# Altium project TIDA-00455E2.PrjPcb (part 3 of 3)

## Sheet uC.SchDoc: uC
size 431 x 279 mm; Date: Not shown in title block; ApprovedBy: Not shown in title block; CheckedBy: Not shown in title block; Author: Not shown in title block; CompanyName: Not shown in title block; DrawnBy: Brian Shaffer; Engineer: Not shown in title block; Organization: Not shown in title block; Address1: Not shown in title block; Address2: Not shown in title block; Address3: Not shown in title block; Address4: Not shown in title block; DocumentNumber: 8; Revision: Use project parameter SCH_Rev; SheetNumber: 8; SheetTotal: 10; PageSetup: Record=PageOptions¦CenterHorizontal=True¦CenterVertical=True¦PrintScale=1.00¦XCorrection=1.00¦YCorrection=1.00¦PrintKind=0¦BorderSize=5000000¦LeftOffset=0¦BottomOffset=0¦Orientation=2¦PaperLength=1000¦PaperWidth=1000¦Scale=100¦PaperSource=15¦PrintQuality=600¦MediaType=1¦DitherType=10¦PaperKind=Letter¦PrintScaleMode=1
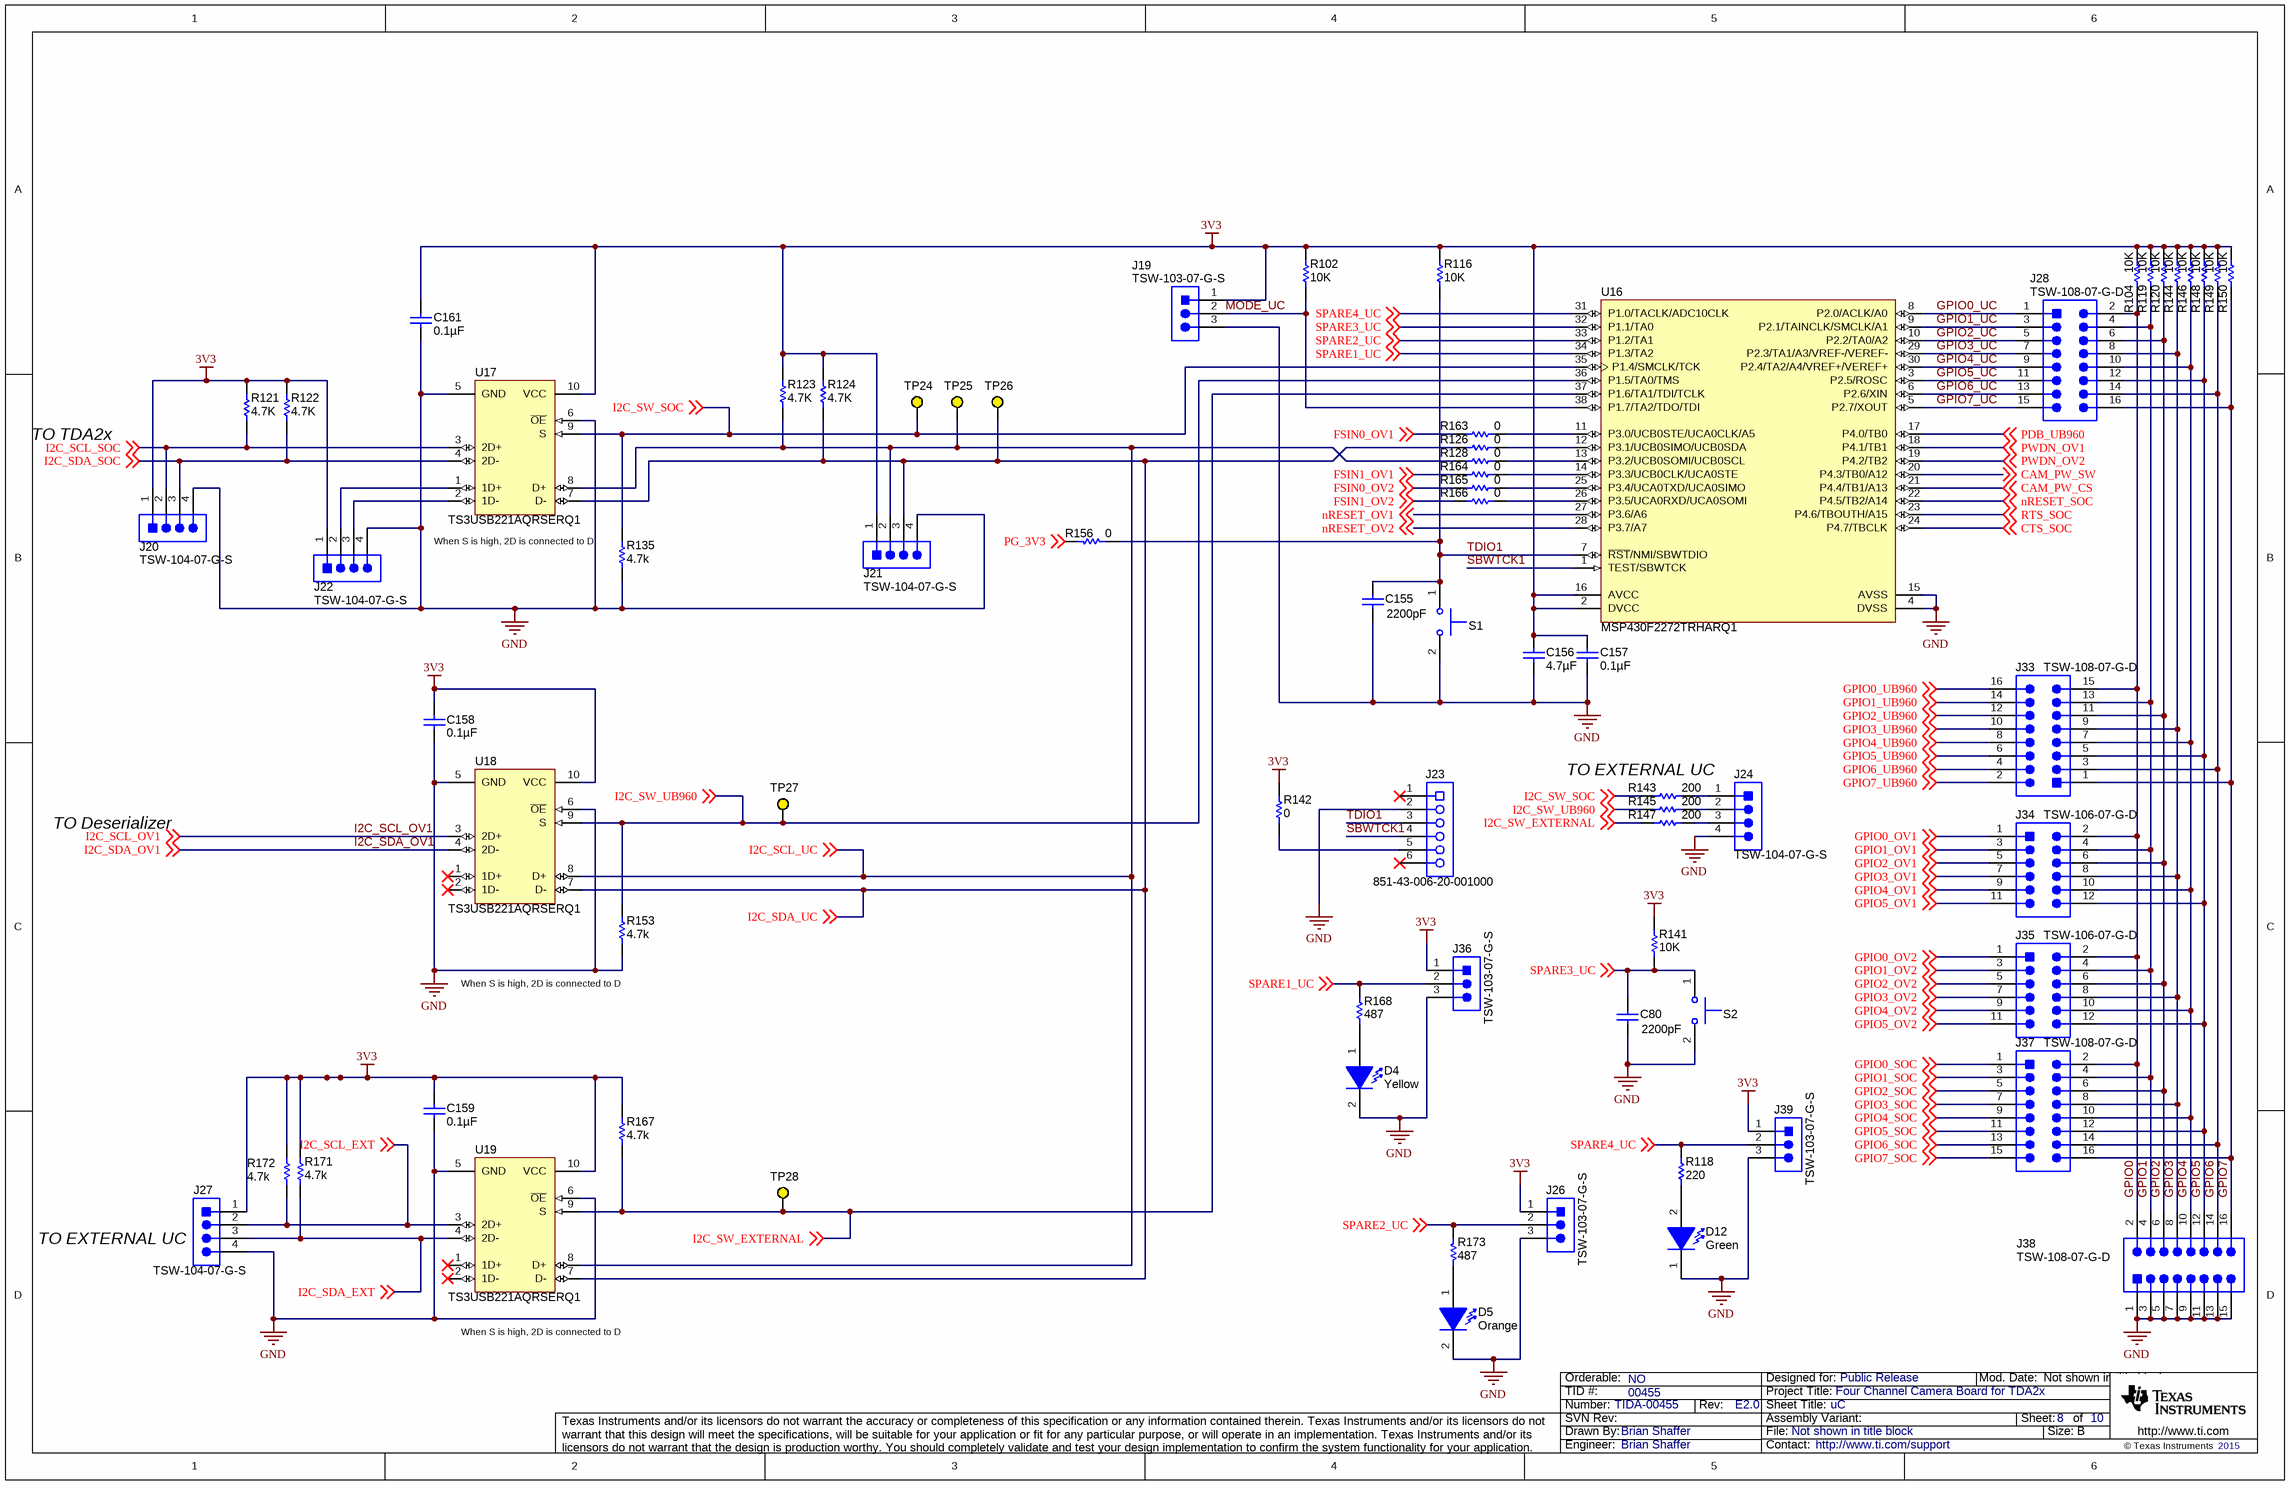
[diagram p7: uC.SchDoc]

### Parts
C80  value 2200pF  [0402]  (hidden comment: UMK105B7222KV-F)
C155  value 2200pF  [0402]  (hidden comment: UMK105B7222KV-F)
C156  ValueDisplayed: 4.7µF  [0805_HV]  (hidden comment: LMK212B7475KG-T)
C157  ValueDisplayed: 0.1µF  [0402]  (hidden comment: GRM155R70J104KA01D)
C158  ValueDisplayed: 0.1µF  [0603]  (hidden comment: 0603YC104JAT2A)
C159  ValueDisplayed: 0.1µF  [0603]  (hidden comment: 0603YC104JAT2A)
C161  ValueDisplayed: 0.1µF  [0603]  (hidden comment: 0603YC104JAT2A)
D4  value Yellow  [LED_SMLP12_Yellow]  (hidden comment: SML-P12YTT86)
D5  value Orange  [LED_SMLP12_ORANGE]  (hidden comment: SML-P12DTT86)
D12  value Green  [SML-P1_GREEN]  (hidden comment: SML-P12PTT86)
J19  TSW-103-07-G-S  [TSW-103-07-G-S]
J20  TSW-104-07-G-S  [TSW-104-07-G-S]
J21  TSW-104-07-G-S  [TSW-104-07-G-S]
J22  TSW-104-07-G-S  [TSW-104-07-G-S]
J23  851-43-006-20-001000  [CONN_851-43-006-20-001000]
J24  TSW-104-07-G-S  [TSW-104-07-G-S]
J26  TSW-103-07-G-S  [TSW-103-07-G-S]
J27  TSW-104-07-G-S  [TSW-104-07-G-S]
J28  TSW-108-07-G-D  [TSW-108-07-G-D]
J33  TSW-108-07-G-D  [TSW-108-07-G-D]
J34  TSW-106-07-G-D  [TSW-106-07-G-D]
J35  TSW-106-07-G-D  [TSW-106-07-G-D]
J36  TSW-103-07-G-S  [TSW-103-07-G-S]
J37  TSW-108-07-G-D  [TSW-108-07-G-D]
J38  TSW-108-07-G-D  [TSW-108-07-G-D]
J39  TSW-103-07-G-S  [TSW-103-07-G-S]
R102  value 10K  [0402]  (hidden comment: CRCW040210K0JNED)
R104  value 10K  [0402]  (hidden comment: CRCW040210K0JNED)
R116  value 10K  [0402]  (hidden comment: CRCW040210K0JNED)
R118  ValueDisplayed: 220  [0402]  (hidden comment: CRCW0402220RJNED)
R119  value 10K  [0402]  (hidden comment: CRCW040210K0JNED)
R120  value 10K  [0402]  (hidden comment: CRCW040210K0JNED)
R121  value 4.7K  [0402]  (hidden comment: CRCW04024K70JNED)
R122  value 4.7K  [0402]  (hidden comment: CRCW04024K70JNED)
R123  value 4.7K  [0402]  (hidden comment: CRCW04024K70JNED)
R124  value 4.7K  [0402]  (hidden comment: CRCW04024K70JNED)
R126  value 0  [0402]  (hidden comment: CRCW04020000Z0ED)
R128  value 0  [0402]  (hidden comment: CRCW04020000Z0ED)
R135  value 4.7k  [0603]  (hidden comment: CRCW06034K70JNEA)
R141  value 10K  [0402]  (hidden comment: CRCW040210K0JNED)
R142  value 0  [0603]  (hidden comment: CRCW06030000Z0EA)
R143  ValueDisplayed: 200  [0402]  (hidden comment: CRCW0402200RJNED)
R144  value 10K  [0402]  (hidden comment: CRCW040210K0JNED)
R145  ValueDisplayed: 200  [0402]  (hidden comment: CRCW0402200RJNED)
R146  value 10K  [0402]  (hidden comment: CRCW040210K0JNED)
R147  ValueDisplayed: 200  [0402]  (hidden comment: CRCW0402200RJNED)
R148  value 10K  [0402]  (hidden comment: CRCW040210K0JNED)
R149  value 10K  [0402]  (hidden comment: CRCW040210K0JNED)
R150  value 10K  [0402]  (hidden comment: CRCW040210K0JNED)
R153  value 4.7k  [0603]  (hidden comment: CRCW06034K70JNEA)
R156  value 0  [0603]  (hidden comment: CRCW06030000Z0EA)
R163  value 0  [0402]  (hidden comment: CRCW04020000Z0ED)
R164  value 0  [0402]  (hidden comment: CRCW04020000Z0ED)
R165  value 0  [0402]  (hidden comment: CRCW04020000Z0ED)
R166  value 0  [0402]  (hidden comment: CRCW04020000Z0ED)
R167  value 4.7k  [0603]  (hidden comment: CRCW06034K70JNEA)
R168  value 487  [0402]  (hidden comment: CRCW0402487RFKED)
R171  value 4.7k  [0603]  (hidden comment: CRCW06034K70JNEA)
R172  value 4.7k  [0603]  (hidden comment: CRCW06034K70JNEA)
R173  value 487  [0402]  (hidden comment: CRCW0402487RFKED)
S1  SKRKAEE010  [SW_SKRKAEE010]  (value not drawn)
S2  SKRKAEE010  [SW_SKRKAEE010]  (value not drawn)
TP24  5004  [Keystone5004]  (value not drawn)
TP25  5004  [Keystone5004]  (value not drawn)
TP26  5004  [Keystone5004]  (value not drawn)
TP27  5004  [Keystone5004]  (value not drawn)
TP28  5004  [Keystone5004]  (value not drawn)
U16  MSP430F2272TRHARQ1  [DA0038A_N]
U17  TS3USB221AQRSERQ1  [RSE0010A]
U18  TS3USB221AQRSERQ1  [RSE0010A]
U19  TS3USB221AQRSERQ1  [RSE0010A]

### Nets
3V3: C156.1 C157.1 C158.1 C159.1 C161.1 J19.1 J20.1 J21.1 J22.1 J26.1 J27.1 J36.1 J39.1 R102.2 R104.2 R116.2 R119.2 R120.2 R121.2 R122.2 R123.2 R124.2 R141.2 R142.2 R144.2 R146.2 R148.2 R149.2 R150.2 R167.2 R171.2 R172.2 U16.2(DVCC) U16.16(AVCC) U17.10(VCC) U18.10(VCC) U19.10(VCC)
GND: C80.2 C155.2 C156.2 C157.2 C158.2 C159.2 C161.2 D4.2(K) D5.2(K) D12.1(K) J19.3 J20.4 J21.4 J22.4 J23.2 J24.4 J26.3 J27.4 J36.3 J38.1 J38.3 J38.5 J38.7 J38.9 J38.11 J38.13 J38.15 J39.3 R135.1 R153.1 S1.2 S2.2 U16.4(DVSS) U16.15(AVSS) U17.5(GND) U17.6(~{OE}) U18.5(GND) U18.6(~{OE}) U19.5(GND) U19.6(~{OE})
CAM_PW_CS: U16.21(P4.4/TB1/A13) ; off-sheet CAM_PW_CS
CAM_PW_SW: U16.20(P4.3/TB0/A12) ; off-sheet CAM_PW_SW
CTS_SOC: U16.24(P4.7/TBCLK) ; off-sheet CTS_SOC
FSIN0_OV1: R163.1 ; off-sheet FSIN0_OV1
FSIN0_OV2: R165.1 ; off-sheet FSIN0_OV2
FSIN1_OV1: R164.1 ; off-sheet FSIN1_OV1
FSIN1_OV2: R166.1 ; off-sheet FSIN1_OV2
GPIO0: J28.2 J33.15 J34.2 J35.2 J37.2 J38.2 R104.1
GPIO0_OV1: J34.1 ; off-sheet GPIO0_OV1
GPIO0_OV2: J35.1 ; off-sheet GPIO0_OV2
GPIO0_SOC: J37.1 ; off-sheet GPIO0_SOC
GPIO0_UB960: J33.16 ; off-sheet GPIO0_UB960
GPIO0_UC: J28.1 U16.8(P2.0/ACLK/A0)
GPIO1: J28.4 J33.13 J34.4 J35.4 J37.4 J38.4 R119.1
GPIO1_OV1: J34.3 ; off-sheet GPIO1_OV1
GPIO1_OV2: J35.3 ; off-sheet GPIO1_OV2
GPIO1_SOC: J37.3 ; off-sheet GPIO1_SOC
GPIO1_UB960: J33.14 ; off-sheet GPIO1_UB960
GPIO1_UC: J28.3 U16.9(P2.1/TAINCLK/SMCLK/A1)
GPIO2: J28.6 J33.11 J34.6 J35.6 J37.6 J38.6 R120.1
GPIO2_OV1: J34.5 ; off-sheet GPIO2_OV1
GPIO2_OV2: J35.5 ; off-sheet GPIO2_OV2
GPIO2_SOC: J37.5 ; off-sheet GPIO2_SOC
GPIO2_UB960: J33.12 ; off-sheet GPIO2_UB960
GPIO2_UC: J28.5 U16.10(P2.2/TA0/A2)
GPIO3: J28.8 J33.9 J34.8 J35.8 J37.8 J38.8 R144.1
GPIO3_OV1: J34.7 ; off-sheet GPIO3_OV1
GPIO3_OV2: J35.7 ; off-sheet GPIO3_OV2
GPIO3_SOC: J37.7 ; off-sheet GPIO3_SOC
GPIO3_UB960: J33.10 ; off-sheet GPIO3_UB960
GPIO3_UC: J28.7 U16.29(P2.3/TA1/A3/VREF-/VEREF-)
GPIO4: J28.10 J33.7 J34.10 J35.10 J37.10 J38.10 R146.1
GPIO4_OV1: J34.9 ; off-sheet GPIO4_OV1
GPIO4_OV2: J35.9 ; off-sheet GPIO4_OV2
GPIO4_SOC: J37.9 ; off-sheet GPIO4_SOC
GPIO4_UB960: J33.8 ; off-sheet GPIO4_UB960
GPIO4_UC: J28.9 U16.30(P2.4/TA2/A4/VREF+/VEREF+)
GPIO5: J28.12 J33.5 J34.12 J35.12 J37.12 J38.12 R148.1
GPIO5_OV1: J34.11 ; off-sheet GPIO5_OV1
GPIO5_OV2: J35.11 ; off-sheet GPIO5_OV2
GPIO5_SOC: J37.11 ; off-sheet GPIO5_SOC
GPIO5_UB960: J33.6 ; off-sheet GPIO5_UB960
GPIO5_UC: J28.11 U16.3(P2.5/ROSC)
GPIO6: J28.14 J33.3 J37.14 J38.14 R149.1
GPIO6_SOC: J37.13 ; off-sheet GPIO6_SOC
GPIO6_UB960: J33.4 ; off-sheet GPIO6_UB960
GPIO6_UC: J28.13 U16.6(P2.6/XIN)
GPIO7: J28.16 J33.1 J37.16 J38.16 R150.1
GPIO7_SOC: J37.15 ; off-sheet GPIO7_SOC
GPIO7_UB960: J33.2 ; off-sheet GPIO7_UB960
GPIO7_UC: J28.15 U16.5(P2.7/XOUT)
I2C_SCL_EXT: J27.2 R172.1 U19.3(2D+) ; off-sheet I2C_SCL_EXT
I2C_SCL_OV1: U18.3(2D+) ; off-sheet I2C_SCL_OV1
I2C_SCL_SOC: J20.2 R121.1 U17.3(2D+) ; off-sheet I2C_SCL_SOC
I2C_SCL_UC: J21.2 R123.1 R128.1 TP25.1 U17.8(D+) U18.8(D+) U19.8(D+) ; off-sheet I2C_SCL_UC
I2C_SDA_EXT: J27.3 R171.1 U19.4(2D-) ; off-sheet I2C_SDA_EXT
I2C_SDA_OV1: U18.4(2D-) ; off-sheet I2C_SDA_OV1
I2C_SDA_SOC: J20.3 R122.1 U17.4(2D-) ; off-sheet I2C_SDA_SOC
I2C_SDA_UC: J21.3 R124.1 R126.1 TP26.1 U17.7(D-) U18.7(D-) U19.7(D-) ; off-sheet I2C_SDA_UC
I2C_SW_EXTERNAL: R147.1 R167.1 TP28.1 U16.37(P1.6/TA1/TDI/TCLK) U19.9(S) ; off-sheet I2C_SW_EXTERNAL
I2C_SW_SOC: R135.2 R143.1 TP24.1 U16.35(P1.4/SMCLK/TCK) U17.9(S) ; off-sheet I2C_SW_SOC
I2C_SW_UB960: R145.1 R153.2 TP27.1 U16.36(P1.5/TA0/TMS) U18.9(S) ; off-sheet I2C_SW_UB960
MODE_UC: J19.2 R102.1 U16.38(P1.7/TA2/TDO/TDI)
nRESET_OV1: U16.27(P3.6/A6) ; off-sheet nRESET_OV1
nRESET_OV2: U16.28(P3.7/A7) ; off-sheet nRESET_OV2
nRESET_SOC: U16.22(P4.5/TB2/A14) ; off-sheet nRESET_SOC
PDB_UB960: U16.17(P4.0/TB0) ; off-sheet PDB_UB960
PG_3V3: R156.2 ; off-sheet PG_3V3
PWDN_OV1: U16.18(P4.1/TB1) ; off-sheet PWDN_OV1
PWDN_OV2: U16.19(P4.2/TB2) ; off-sheet PWDN_OV2
RTS_SOC: U16.23(P4.6/TBOUTH/A15) ; off-sheet RTS_SOC
SBWTCK1: J23.4 U16.1(TEST/SBWTCK)
SPARE1_UC: J36.2 R168.2 U16.34(P1.3/TA2) ; off-sheet SPARE1_UC
SPARE2_UC: J26.2 R173.2 U16.33(P1.2/TA1) ; off-sheet SPARE2_UC
SPARE3_UC: C80.1 R141.1 S2.1 U16.32(P1.1/TA0) ; off-sheet SPARE3_UC
SPARE4_UC: J39.2 R118.2 U16.31(P1.0/TACLK/ADC10CLK) ; off-sheet SPARE4_UC
TDIO1: C155.1 J23.3 R116.1 R156.1 S1.1 U16.7(~{RST}/NMI/SBWTDIO)
NetD4_1: D4.1(A) R168.1
NetD5_1: D5.1(A) R173.1
NetD12_2: D12.2(A) R118.1
NetJ22_2: J22.2 U17.1(1D+)
NetJ22_3: J22.3 U17.2(1D-)
NetJ23_5: J23.5 R142.1
NetJ24_1: J24.1 R143.2
NetJ24_2: J24.2 R145.2
NetJ24_3: J24.3 R147.2
NetR126_2: R126.2 U16.12(P3.1/UCB0SIMO/UCB0SDA)
NetR128_2: R128.2 U16.13(P3.2/UCB0SOMI/UCB0SCL)
NetR163_2: R163.2 U16.11(P3.0/UCB0STE/UCA0CLK/A5)
NetR164_2: R164.2 U16.14(P3.3/UCB0CLK/UCA0STE)
NetR165_2: R165.2 U16.25(P3.4/UCA0TXD/UCA0SIMO)
NetR166_2: R166.2 U16.26(P3.5/UCA0RXD/UCA0SOMI)

Not connected (* = marked no-connect by the designer): J23 1* 6*; U18 1(1D+)* 2(1D-)*; U19 1(1D+)* 2(1D-)*

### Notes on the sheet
- TO TDA2x
- (near R135) When S is high, 2D is connected to D
- (near R143) TO EXTERNAL UC
- TO Deserializer
- (near R153) When S is high, 2D is connected to D
- (near J27) TO EXTERNAL UC
- (near U19) When S is high, 2D is connected to D

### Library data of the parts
C80 C155 = Capacitor: Cap, Cer-X7R, 2200pF, 50V, 10%, 0402; Manufacturer: Taiyo Yuden; PART Name: SCH_LIB\CAP_NP; Polarized: N; U/M: EA; TempCo: X7R; DECAL Name: 0402,0402_HD; EN: 102-1-00062; Onhand: 7818
C156 = LMK212B7475KG-T: Cap, Cer-X7R, 4.7uF, 10V, 10%, 0805; Manufacturer: Taiyo Yuden; PART Name: SCH_LIB\CAP_NP; Polarized: N; CompType: Capacitor; U/M: EA; Cap_F: 0.0000047; Tolerance_%: 10; Value1: Unknown; TempCo: X7R; TaMin_C: -55; TaMax_C: 125; Cap_Case: 0805; EN: 102-1-00281; Onhand: 27
C157 = GRM155R70J104KA01D: Cap, Cer-X7R, 0.1uF, 6.3V, 10%, 0402; Manufacturer: MuRata; Polarized: N; CompType: Capacitor; U/M: EA; Cap_F: 0.0000001; Tolerance_%: 10; Value1: Unknown; VDC_V: 6.3; TempCo: X7R; TaMin_C: -55; TaMax_C: 125; EN: 102-1-01892; Mfg: MURATA MANUFACTURING CO,LTD; Onhand: 0
C158 C159 C161 = 0603YC104JAT2A: CAP, CERM, 0.1uF, 16V, +/-5%, X7R, 0603; Manufacturer: AVX; Polarized: N; CompType: Capacitor; U/M: EA; Cap_F: 0.0000001; Tolerance_%: 5; ESR_Ohm: 0.039; Value1: 0.039 ohm; VDC_V: 16; TaMin_C: -55; TaMax_C: 125
D4 = SML-P12YTT86: LED, Yellow, SMD; Manufacturer: Rohm; Type: InGaN; Vf_V: 2.1; Value2: 2.1V; Io_A: 0.02; Tjmax_C: 85; Value1: W; U/M: EA
D5 = SML-P12DTT86: LED, Orange, SMD; Manufacturer: Rohm; Type: InGaN; Vf_V: 2.1; Value2: 2.1V; Io_A: 0.02; Tjmax_C: 85; Value1: W; U/M: EA
D12 = SML-P12PTT86: LED, Green, SMD; Manufacturer: Rohm; Type: AlInGaP; Vf_V: 2.2; Value2: 2.2V; Io_A: 0.02; Value1: W; U/M: EA
J19 J26 J36 J39 = TSW-103-07-G-S: Header, 100mil, 3x1, Gold, TH; Manufacturer: Samtec; SymbolCreator: a0799628; U/M: EA
J20-J22 J24 J27 = TSW-104-07-G-S: Header, 100mil, 4x1, Gold, TH; Manufacturer: Samtec; SymbolCreator: a0412235; U/M: EA
J23 = 851-43-006-20-001000: Receptacle, 50mil, 6x1, Gold, R/A, TH; Manufacturer: Mill-Max; SymbolCreator: a0411947; U/M: EA
J28 J33 J37 J38 = TSW-108-07-G-D: Header, 100mil, 8x2, Gold, TH; Manufacturer: Samtec; SymbolCreator: a0412235; U/M: EA
J34 J35 = TSW-106-07-G-D: Header, 100mil, 6x2, Gold, TH; Manufacturer: Samtec; SymbolCreator: a0412235; U/M: EA
R102 R104 R116 R119 R120 R141 R144 R146 R148-R150 = CRCW040210K0JNED: Res, Chip, 10K, 1/16W, 5%, 0402; Manufacturer: Vishay-Dale; PART Name: SCH_LIB\RES; CompType: Resistor; Res_ohm: 10000; Value_Code: 10k0; Tolerance_%: 5; Power_W: 0.063; Value2: 0.063W; VDC_V: 50; TempCo: 200 ppm/C; EIA_Code: E24; U/M: EA; EN: 101-1-02793; Mfg: VISHAY; Onhand: 7938
R118 = CRCW0402220RJNED: RES, 220, 5%, 0.063 W, 0402; Manufacturer: Vishay-Dale; CompType: Resistor; Value: 220; Value_Code: 220R; Tolerance_%: 5; Power_W: 0.063; Value2: 0.063W; VDC_V: 50; TempCo: 200 ppm/C; EIA_Code: E24; U/M: EA
R121-R124 = CRCW04024K70JNED: Res, Chip, 4.7K, 1/16W, 5%, 0402; Manufacturer: Vishay-Dale; PART Name: SCH_LIB\RES; CompType: Resistor; Res_ohm: 4700; Value_Code: 4k70; Tolerance_%: 5; Power_W: 0.063; Value2: 0.063W; VDC_V: 50; TempCo: 200 ppm/C; EIA_Code: E24; U/M: EA; DECAL Name: 0402,0402_HD; EN: 101-1-02785; Mfg: VISHAY; Onhand: 6860
R126 R128 R163-R166 = CRCW04020000Z0ED: RES, 0 ohm, 5%, 0.063W, 0402; Manufacturer: Vishay-Dale; CompType: Resistor; Value_Code: 0000; Tolerance_%: 5; Power_W: 0.063; VDC_V: 50; TempCo: 200 ppm/C; EIA_Code: E24; U/M: EA; EN: 101-1-00001
R135 R153 R167 R171 R172 = CRCW06034K70JNEA: RES, 4.7k ohm, 5%, 0.1W, 0603; Manufacturer: Vishay-Dale; CompType: Resistor; Res_ohm: 4700; Value_Code: 4k70; Tolerance_%: 5; Power_W: 0.1; VDC_V: 75; TempCo: 200 ppm/C; EIA_Code: E24; U/M: EA
R142 = CRCW06030000Z0EA: RES, 0 ohm, 5%, 0.1W, 0603; Manufacturer: Vishay-Dale; CompType: Resistor; Value_Code: 0000; Tolerance_%: 5; Power_W: 0.1; VDC_V: 75; TempCo: 200 ppm/C; EIA_Code: E24; U/M: EA; EN: 101-1-03483
R143 R145 R147 = CRCW0402200RJNED: RES, 200, 5%, 0.063 W, 0402; Manufacturer: Vishay-Dale; CompType: Resistor; Value: 200; Value_Code: 200R; Tolerance_%: 5; Power_W: 0.063; Value2: 0.063W; VDC_V: 50; TempCo: 200 ppm/C; EIA_Code: E24; U/M: EA
R156 = CRCW06030000Z0EA: RES, 0 ohm, 5%, 0.1W, 0603; Manufacturer: Vishay-Dale; CompType: Resistor; Value_Code: 0000; Tolerance_%: 5; Power_W: 0.1; VDC_V: 75; TempCo: 200 ppm/C; EIA_Code: E24; U/M: EA
R168 R173 = CRCW0402487RFKED: RES, 487 ohm, 1%, 0.063W, 0402; Manufacturer: Vishay-Dale; Alternate Manufacturer: Any; Alternate PartNumber: Equivalent; CompType: Resistor; Value_Code: 487R; Tolerance_%: 1; Power_W: 0.063; VDC_V: 50; TempCo: 100 ppm/C; EIA_Code: E96; U/M: EA
S1 S2 = SKRKAEE010: Switch, Tactile, 12v, 50mA, Vertical, SMD; Manufacturer: Alps; Alternate Manufacturer: Any; Alternate PartNumber: Equivalent; SymbolCreator: a0412235; Circuit: SPST-NO; VDC_V: 12; SwitchFunction: Off-Mom; PositionCount: 1; CurrentRating_mA: 50; EN: 205-1-00046; Mfg: ALPS ELECTRIC CO., LTD; Onhand: 0
TP24-TP28 = 5004: Test Point, Miniature, Yellow, TH; Manufacturer: Keystone; CompType: Test Point Loop; U/M: EA
U16 = MSP430F2272TDAQ1: 16 MHz Mixed Signal Microcontroller with 32 KB Flash, 1024 B SARM and 32 GPIOs, -40 to 105 degC, 38-pin SOP (DA); Alternate Manufacturer: Texas Instruments; Alternate PartNumber: Equivalent; ADC: 10-bit SAR; ADC Channels: 12; Brown Out Reset: Yes; Eco-Plan: TBD; Flash(KB): 32; Frequency(MHz): 16; Pin/Package: 38TSSOP, 40VQFN; SRAM(B): 1024; SubFamily: Automotive, Extended Temp; Timers - 16-bit: 2; USCI_A (UART/LIN/IrDA/SPI): 1
U17 = TS3USB221AQRSERQ1: IC, TS3USB221A-Q1, Dual USB Switch, UQFN-10; Manufacturer: Texas Instruments; Alternate Manufacturer: None; Alternate PartNumber: Equivalent; Eco-Plan: Green (RoHS & no Sb/Br); Number of Channels: 2; Architecture: 1; ESD HBM(kV): +/-7; ICC(uA): 30; tpd max(ns): 0.25; ron(max)(ohms): 16; RON Mis-match(Max)(Ohms): 0.2; Bandwidth(MHz): 900; ON Time(Max)(ns): 12; EN: 301-0-00624; Onhand: 0
U18 U19 = TS3USB221AQRSERQ1: Automotive Catalog ESD Protected, High-Speed USB 2.0 (480-Mbps) 1:2 Multiplexer / Demultiplexer Switch, 16 ohm RON, 2.5 to 3.3V, -40 to 125 degC, 10-Pin UQFN (RSE), Green (RoHS & no Sb/Br); Manufacturer: Texas Instruments; Alternate Manufacturer: None; Alternate PartNumber: Equivalent; SubFamily: USB Switch; Number of Channels: 2; Architecture: 1; ESD HBM(kV): +/-7; ICC(uA): 30; tpd max(ns): 0.25; ron(max)(ohms): 16; RON Mis-match(Max)(Ohms): 0.2; Bandwidth(MHz): 900; ON Time(Max)(ns): 12

## Sheet TDA2x_Conector.SchDoc: TDA2x_Conector
size 431 x 279 mm; Date: Not shown in title block; ApprovedBy: Not shown in title block; CheckedBy: Not shown in title block; Author: Not shown in title block; CompanyName: Not shown in title block; DrawnBy: Brian Shaffer; Engineer: Not shown in title block; Organization: Not shown in title block; Address1: Not shown in title block; Address2: Not shown in title block; Address3: Not shown in title block; Address4: Not shown in title block; DocumentNumber: 9; Revision: Use project parameter SCH_Rev; SheetNumber: 9; SheetTotal: 10; PageSetup: Record=PageOptions¦CenterHorizontal=True¦CenterVertical=True¦PrintScale=0.96¦XCorrection=1.00¦YCorrection=1.00¦PrintKind=0¦BorderSize=5000000¦LeftOffset=0¦BottomOffset=0¦Orientation=2¦PaperLength=1000¦PaperWidth=1000¦Scale=100¦PaperSource=15¦PrintQuality=-3¦MediaType=1¦DitherType=10¦PrintScaleMode=1¦PaperKind=11x17¦PaperIndex=17
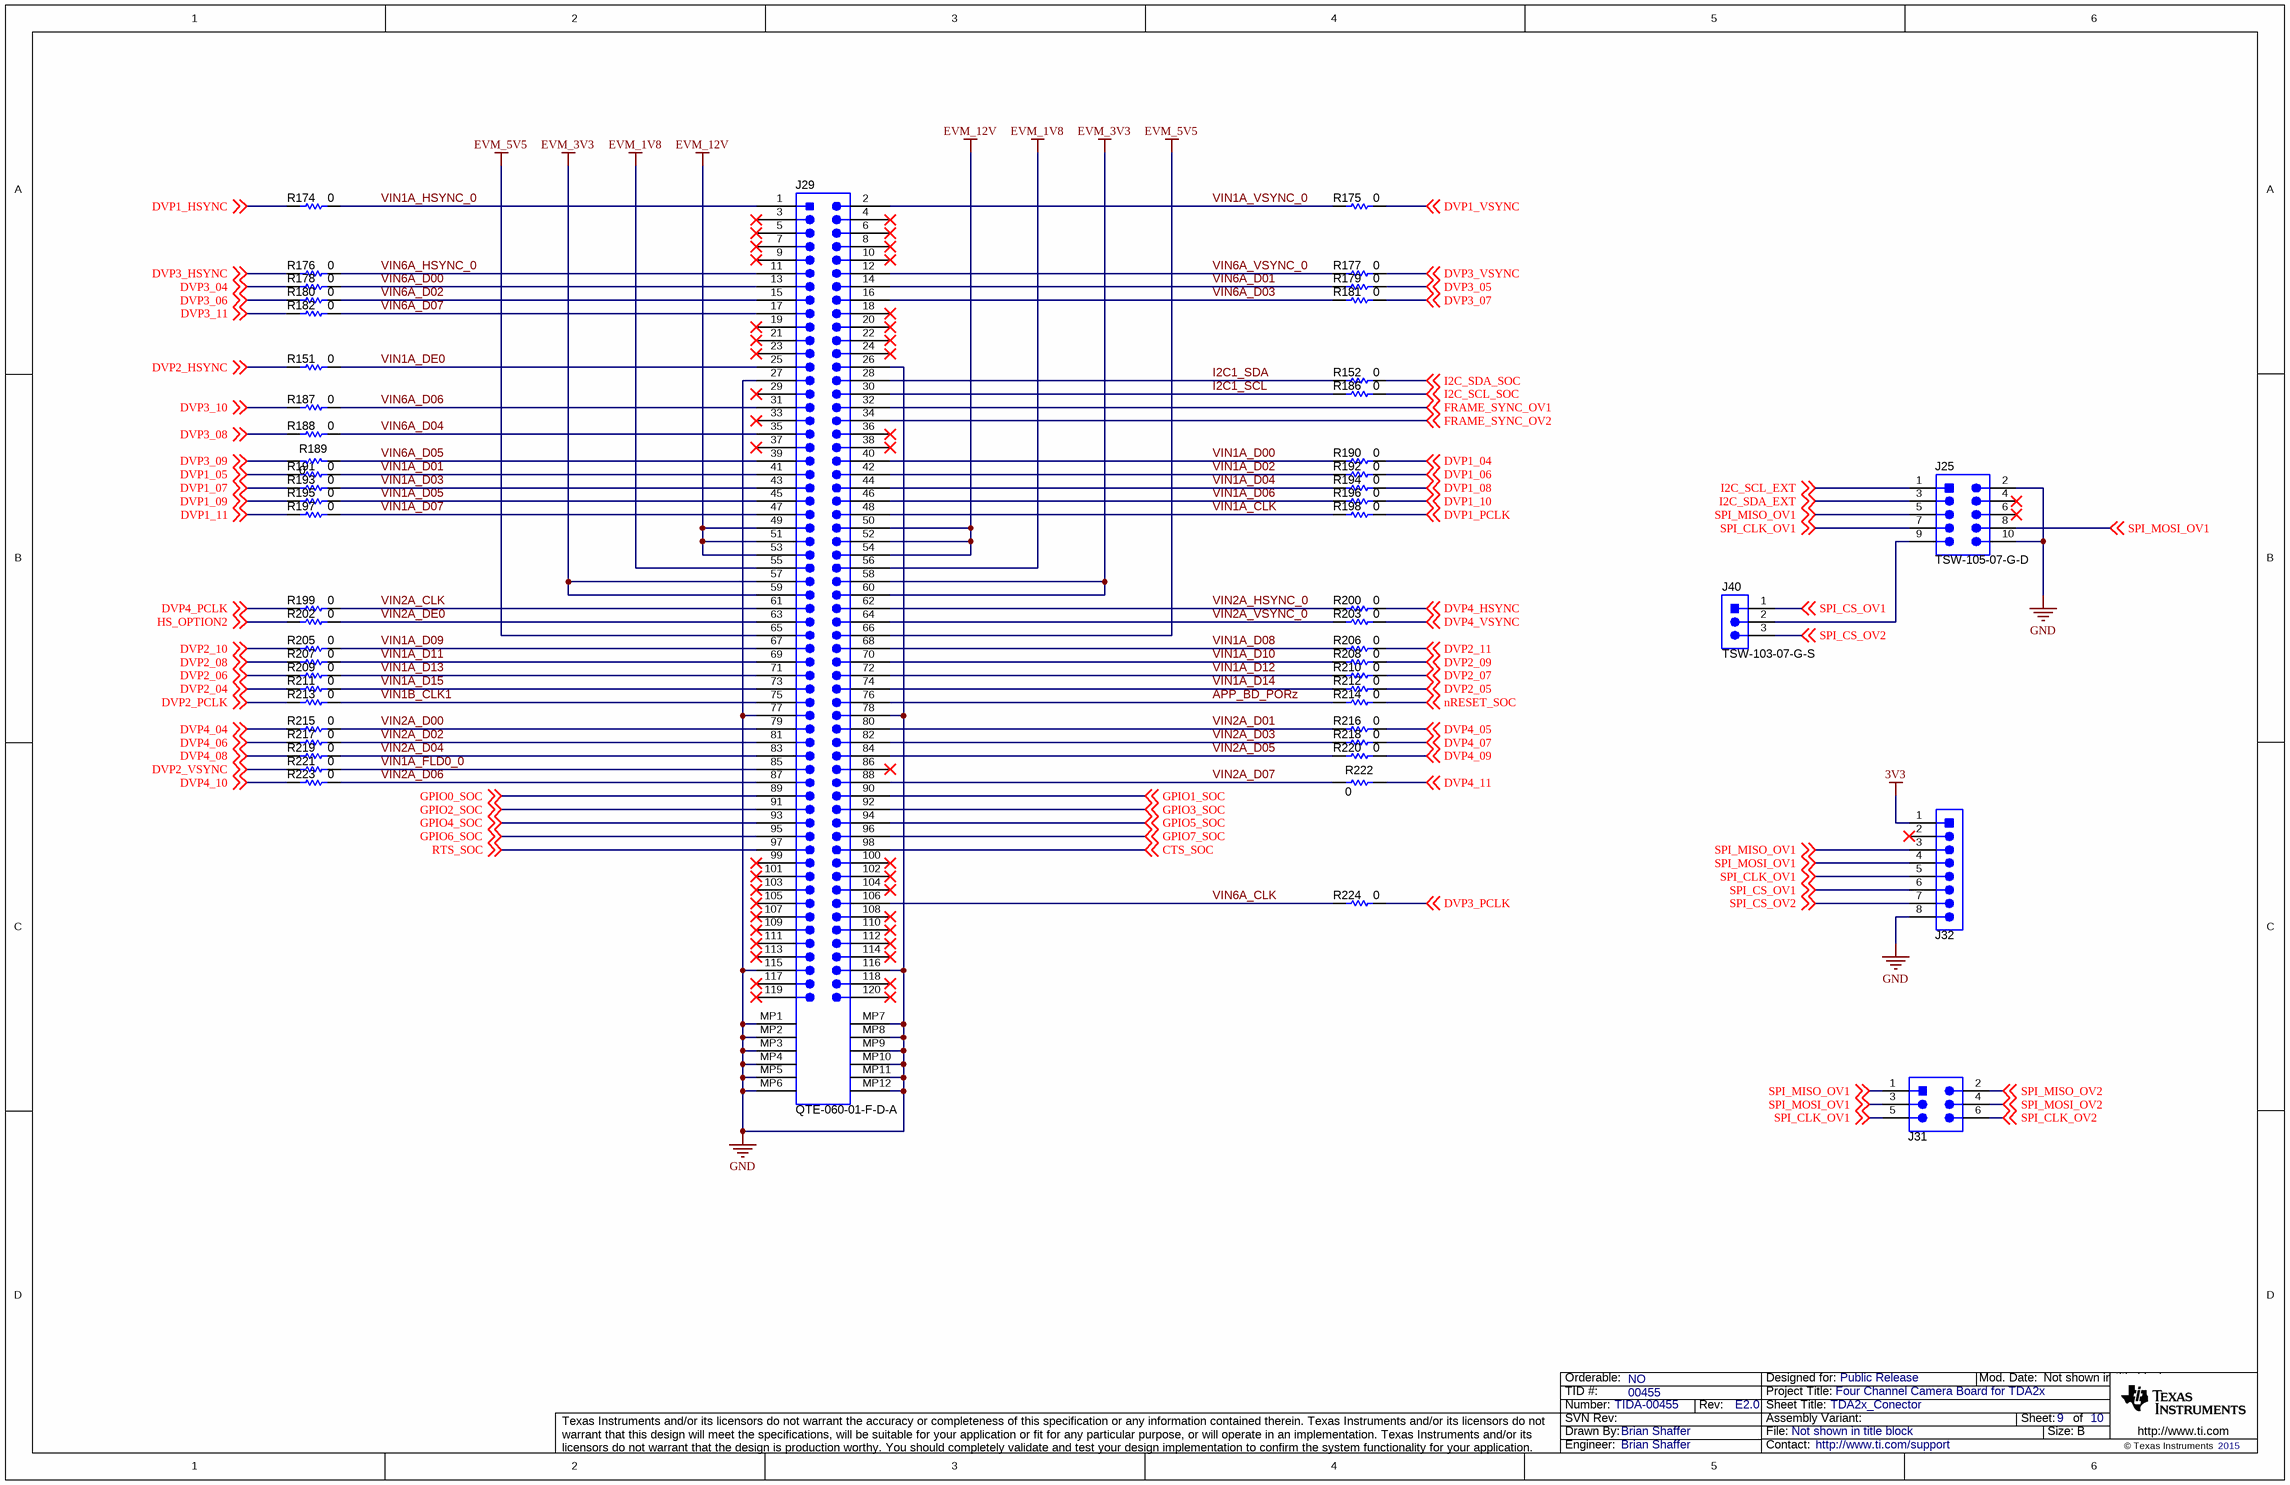
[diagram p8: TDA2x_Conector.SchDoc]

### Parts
J25  TSW-105-07-G-D  [TSW-105-07-G-D]
J29  QTE-060-01-F-D-A  [Samtec_QTE-060-01-x-D-A]
J31  TSW-103-07-G-D  [TSW-103-07-G-D]  (value not drawn)
J32  TSW-108-07-G-S  [TSW-108-07-G-S]  (value not drawn)
J40  TSW-103-07-G-S  [TSW-103-07-G-S]
R151  value 0  [0402]  (hidden comment: ERJ-2GE0R00X)
R152  value 0  [0402]  (hidden comment: ERJ-2GE0R00X)
R174  value 0  [0402]  (hidden comment: ERJ-2GE0R00X)
R175  value 0  [0402]  (hidden comment: ERJ-2GE0R00X)
R176  value 0  [0402]  (hidden comment: ERJ-2GE0R00X)
R177  value 0  [0402]  (hidden comment: ERJ-2GE0R00X)
R178  value 0  [0402]  (hidden comment: ERJ-2GE0R00X)
R179  value 0  [0402]  (hidden comment: ERJ-2GE0R00X)
R180  value 0  [0402]  (hidden comment: ERJ-2GE0R00X)
R181  value 0  [0402]  (hidden comment: ERJ-2GE0R00X)
R182  value 0  [0402]  (hidden comment: ERJ-2GE0R00X)
R186  value 0  [0402]  (hidden comment: ERJ-2GE0R00X)
R187  value 0  [0402]  (hidden comment: ERJ-2GE0R00X)
R188  value 0  [0402]  (hidden comment: ERJ-2GE0R00X)
R189  value 0  [0402]  (hidden comment: ERJ-2GE0R00X)
R190  value 0  [0402]  (hidden comment: ERJ-2GE0R00X)
R191  value 0  [0402]  (hidden comment: ERJ-2GE0R00X)
R192  value 0  [0402]  (hidden comment: ERJ-2GE0R00X)
R193  value 0  [0402]  (hidden comment: ERJ-2GE0R00X)
R194  value 0  [0402]  (hidden comment: ERJ-2GE0R00X)
R195  value 0  [0402]  (hidden comment: ERJ-2GE0R00X)
R196  value 0  [0402]  (hidden comment: ERJ-2GE0R00X)
R197  value 0  [0402]  (hidden comment: ERJ-2GE0R00X)
R198  value 0  [0402]  (hidden comment: ERJ-2GE0R00X)
R199  value 0  [0402]  (hidden comment: ERJ-2GE0R00X)
R200  value 0  [0402]  (hidden comment: ERJ-2GE0R00X)
R202  value 0  [0402]  (hidden comment: ERJ-2GE0R00X)
R203  value 0  [0402]  (hidden comment: ERJ-2GE0R00X)
R205  value 0  [0402]  (hidden comment: ERJ-2GE0R00X)
R206  value 0  [0402]  (hidden comment: ERJ-2GE0R00X)
R207  value 0  [0402]  (hidden comment: ERJ-2GE0R00X)
R208  value 0  [0402]  (hidden comment: ERJ-2GE0R00X)
R209  value 0  [0402]  (hidden comment: ERJ-2GE0R00X)
R210  value 0  [0402]  (hidden comment: ERJ-2GE0R00X)
R211  value 0  [0402]  (hidden comment: ERJ-2GE0R00X)
R212  value 0  [0402]  (hidden comment: ERJ-2GE0R00X)
R213  value 0  [0402]  (hidden comment: ERJ-2GE0R00X)
R214  value 0  [0402]  (hidden comment: ERJ-2GE0R00X)
R215  value 0  [0402]  (hidden comment: ERJ-2GE0R00X)
R216  value 0  [0402]  (hidden comment: ERJ-2GE0R00X)
R217  value 0  [0402]  (hidden comment: ERJ-2GE0R00X)
R218  value 0  [0402]  (hidden comment: ERJ-2GE0R00X)
R219  value 0  [0402]  (hidden comment: ERJ-2GE0R00X)
R220  value 0  [0402]  (hidden comment: ERJ-2GE0R00X)
R221  value 0  [0402]  (hidden comment: ERJ-2GE0R00X)
R222  value 0  [0402]  (hidden comment: ERJ-2GE0R00X)
R223  value 0  [0402]  (hidden comment: ERJ-2GE0R00X)
R224  value 0  [0402]  (hidden comment: ERJ-2GE0R00X)

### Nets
3V3: J32.1
EVM_1V8: J29.55 J29.56
EVM_3V3: J29.57 J29.58 J29.59 J29.60
EVM_5V5: J29.65 J29.66
EVM_12V: J29.49 J29.50 J29.51 J29.52 J29.53 J29.54
GND: J25.2 J25.10 J29.26 J29.27 J29.77 J29.78 J29.115 J29.116 J29.MP1 J29.MP2 J29.MP3 J29.MP4 J29.MP5 J29.MP6 J29.MP7 J29.MP8 J29.MP9 J29.MP10 J29.MP11 J29.MP12 J32.8
APP_BD_PORz: J29.76 R214.1
CTS_SOC: J29.98 ; off-sheet CTS_SOC
DVP1_04: R190.2 ; off-sheet DVP1_04
DVP1_05: R191.1 ; off-sheet DVP1_05
DVP1_06: R192.2 ; off-sheet DVP1_06
DVP1_07: R193.1 ; off-sheet DVP1_07
DVP1_08: R194.2 ; off-sheet DVP1_08
DVP1_09: R195.1 ; off-sheet DVP1_09
DVP1_10: R196.2 ; off-sheet DVP1_10
DVP1_11: R197.1 ; off-sheet DVP1_11
DVP1_HSYNC: R174.1 ; off-sheet DVP1_HSYNC
DVP1_PCLK: R198.2 ; off-sheet DVP1_PCLK
DVP1_VSYNC: R175.2 ; off-sheet DVP1_VSYNC
DVP2_04: R211.1 ; off-sheet DVP2_04
DVP2_05: R212.2 ; off-sheet DVP2_05
DVP2_06: R209.1 ; off-sheet DVP2_06
DVP2_07: R210.2 ; off-sheet DVP2_07
DVP2_08: R207.1 ; off-sheet DVP2_08
DVP2_09: R208.2 ; off-sheet DVP2_09
DVP2_10: R205.1 ; off-sheet DVP2_10
DVP2_11: R206.2 ; off-sheet DVP2_11
DVP2_HSYNC: R151.1 ; off-sheet DVP2_HSYNC
DVP2_PCLK: R213.1 ; off-sheet DVP2_PCLK
DVP2_VSYNC: R221.1 ; off-sheet DVP2_VSYNC
DVP3_04: R178.1 ; off-sheet DVP3_04
DVP3_05: R179.2 ; off-sheet DVP3_05
DVP3_06: R180.1 ; off-sheet DVP3_06
DVP3_07: R181.2 ; off-sheet DVP3_07
DVP3_08: R188.1 ; off-sheet DVP3_08
DVP3_09: R189.2 ; off-sheet DVP3_09
DVP3_10: R187.1 ; off-sheet DVP3_10
DVP3_11: R182.1 ; off-sheet DVP3_11
DVP3_HSYNC: R176.1 ; off-sheet DVP3_HSYNC
DVP3_PCLK: R224.2 ; off-sheet DVP3_PCLK
DVP3_VSYNC: R177.2 ; off-sheet DVP3_VSYNC
DVP4_04: R215.1 ; off-sheet DVP4_04
DVP4_05: R216.2 ; off-sheet DVP4_05
DVP4_06: R217.1 ; off-sheet DVP4_06
DVP4_07: R218.2 ; off-sheet DVP4_07
DVP4_08: R219.1 ; off-sheet DVP4_08
DVP4_09: R220.2 ; off-sheet DVP4_09
DVP4_10: R223.1 ; off-sheet DVP4_10
DVP4_11: R222.2 ; off-sheet DVP4_11
DVP4_HSYNC: R200.2 ; off-sheet DVP4_HSYNC
DVP4_PCLK: R199.1 ; off-sheet DVP4_PCLK
DVP4_VSYNC: R203.2 ; off-sheet DVP4_VSYNC
FRAME_SYNC_OV1: J29.32 ; off-sheet FRAME_SYNC_OV1
FRAME_SYNC_OV2: J29.34 ; off-sheet FRAME_SYNC_OV2
GPIO0_SOC: J29.89 ; off-sheet GPIO0_SOC
GPIO1_SOC: J29.90 ; off-sheet GPIO1_SOC
GPIO2_SOC: J29.91 ; off-sheet GPIO2_SOC
GPIO3_SOC: J29.92 ; off-sheet GPIO3_SOC
GPIO4_SOC: J29.93 ; off-sheet GPIO4_SOC
GPIO5_SOC: J29.94 ; off-sheet GPIO5_SOC
GPIO6_SOC: J29.95 ; off-sheet GPIO6_SOC
GPIO7_SOC: J29.96 ; off-sheet GPIO7_SOC
HS_OPTION2: R202.1 ; off-sheet HS_OPTION2
I2C1_SCL: J29.30 R186.1
I2C1_SDA: J29.28 R152.1
I2C_SCL_EXT: J25.1 ; off-sheet I2C_SCL_EXT
I2C_SCL_SOC: R186.2 ; off-sheet I2C_SCL_SOC
I2C_SDA_EXT: J25.3 ; off-sheet I2C_SDA_EXT
I2C_SDA_SOC: R152.2 ; off-sheet I2C_SDA_SOC
nRESET_SOC: R214.2 ; off-sheet nRESET_SOC
RTS_SOC: J29.97 ; off-sheet RTS_SOC
SPI_CLK_OV1: J25.7 J31.5 J32.5 ; off-sheet SPI_CLK_OV1
SPI_CLK_OV2: J31.6 ; off-sheet SPI_CLK_OV2
SPI_CS_OV1: J32.6 J40.1 ; off-sheet SPI_CS_OV1
SPI_CS_OV2: J32.7 J40.3 ; off-sheet SPI_CS_OV2
SPI_MISO_OV1: J25.5 J31.1 J32.3 ; off-sheet SPI_MISO_OV1
SPI_MISO_OV2: J31.2 ; off-sheet SPI_MISO_OV2
SPI_MOSI_OV1: J25.8 J31.3 J32.4 ; off-sheet SPI_MOSI_OV1
SPI_MOSI_OV2: J31.4 ; off-sheet SPI_MOSI_OV2
VIN1A_CLK: J29.48 R198.1
VIN1A_D00: J29.40 R190.1
VIN1A_D01: J29.41 R191.2
VIN1A_D02: J29.42 R192.1
VIN1A_D03: J29.43 R193.2
VIN1A_D04: J29.44 R194.1
VIN1A_D05: J29.45 R195.2
VIN1A_D06: J29.46 R196.1
VIN1A_D07: J29.47 R197.2
VIN1A_D08: J29.68 R206.1
VIN1A_D09: J29.67 R205.2
VIN1A_D10: J29.70 R208.1
VIN1A_D11: J29.69 R207.2
VIN1A_D12: J29.72 R210.1
VIN1A_D13: J29.71 R209.2
VIN1A_D14: J29.74 R212.1
VIN1A_D15: J29.73 R211.2
VIN1A_DE0: J29.25 R151.2
VIN1A_FLD0_0: J29.85 R221.2
VIN1A_HSYNC_0: J29.1 R174.2
VIN1A_VSYNC_0: J29.2 R175.1
VIN1B_CLK1: J29.75 R213.2
VIN2A_CLK: J29.61 R199.2
VIN2A_D00: J29.79 R215.2
VIN2A_D01: J29.80 R216.1
VIN2A_D02: J29.81 R217.2
VIN2A_D03: J29.82 R218.1
VIN2A_D04: J29.83 R219.2
VIN2A_D05: J29.84 R220.1
VIN2A_D06: J29.87 R223.2
VIN2A_D07: J29.88 R222.1
VIN2A_DE0: J29.63 R202.2
VIN2A_HSYNC_0: J29.62 R200.1
VIN2A_VSYNC_0: J29.64 R203.1
VIN6A_CLK: J29.106 R224.1
VIN6A_D00: J29.13 R178.2
VIN6A_D01: J29.14 R179.1
VIN6A_D02: J29.15 R180.2
VIN6A_D03: J29.16 R181.1
VIN6A_D04: J29.35 R188.2
VIN6A_D05: J29.39 R189.1
VIN6A_D06: J29.31 R187.2
VIN6A_D07: J29.17 R182.2
VIN6A_HSYNC_0: J29.11 R176.2
VIN6A_VSYNC_0: J29.12 R177.1
NetJ25_9: J25.9 J40.2

Not connected (* = marked no-connect by the designer): J25 4* 6*; J29 3* 4* 5* 6* 7* 8* 9* 10* 18* 19* 20* 21* 22* 23* 24* 29* 33* 36* 37* 38* 86* 99* 100* 101* 102* 103* 104* 105* 107* 108* 109* 110* 111* 112* 113* 114* 117* 118* 119* 120*; J32 2*

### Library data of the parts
J25 = TSW-105-07-G-D: Header, 100mil, 5x2, Gold, TH; Manufacturer: Samtec; SymbolCreator: a0412235; U/M: EA
J29 = QTE-060-01-F-D-A: Header, 0.8mm, 60x2, Gold, SMT; Manufacturer: Samtec; SymbolCreator: Altium; U/M: EA
J31 = TSW-103-07-G-D: Header, 100mil, 3x2, Gold, TH; Manufacturer: Samtec; SymbolCreator: a0412235; U/M: EA
J32 = TSW-108-07-G-S: Header, 100mil, 8x1, Gold, TH; Manufacturer: Samtec; SymbolCreator: a0411947; U/M: EA
J40 = TSW-103-07-G-S: as J19 on sheet uC
R151 R152 R174-R182 R186-R200 R202 R203 R205-R224 = ERJ-2GE0R00X: RES, 0 ohm, 5%, 0.063W, 0402; Manufacturer: Panasonic; CompType: Resistor; Value_Code: 0000; Tolerance_%: 5; Power_W: 0.063; VDC_V: 50; TempCo: 600 ppm/C; EIA_Code: E24; U/M: EA

## Sheet Hardware.SchDoc: Hardware
size 431 x 279 mm; Date: Not shown in title block; ApprovedBy: Not shown in title block; CheckedBy: Not shown in title block; Author: Not shown in title block; CompanyName: Not shown in title block; DrawnBy: Brian Shaffer; Engineer: Not shown in title block; Organization: Not shown in title block; Address1: Not shown in title block; Address2: Not shown in title block; Address3: Not shown in title block; Address4: Not shown in title block; DocumentNumber: 10; Revision: Use project parameter SCH_Rev; SheetNumber: 10; SheetTotal: 10; PageSetup: Record=PageOptions¦CenterHorizontal=True¦CenterVertical=True¦PrintScale=1.00¦XCorrection=1.00¦YCorrection=1.00¦PrintKind=0¦BorderSize=5000000¦LeftOffset=0¦BottomOffset=0¦Orientation=2¦PaperLength=1000¦PaperWidth=1000¦Scale=100¦PaperSource=15¦PrintQuality=600¦MediaType=1¦DitherType=10¦PaperKind=Letter¦PrintScaleMode=1
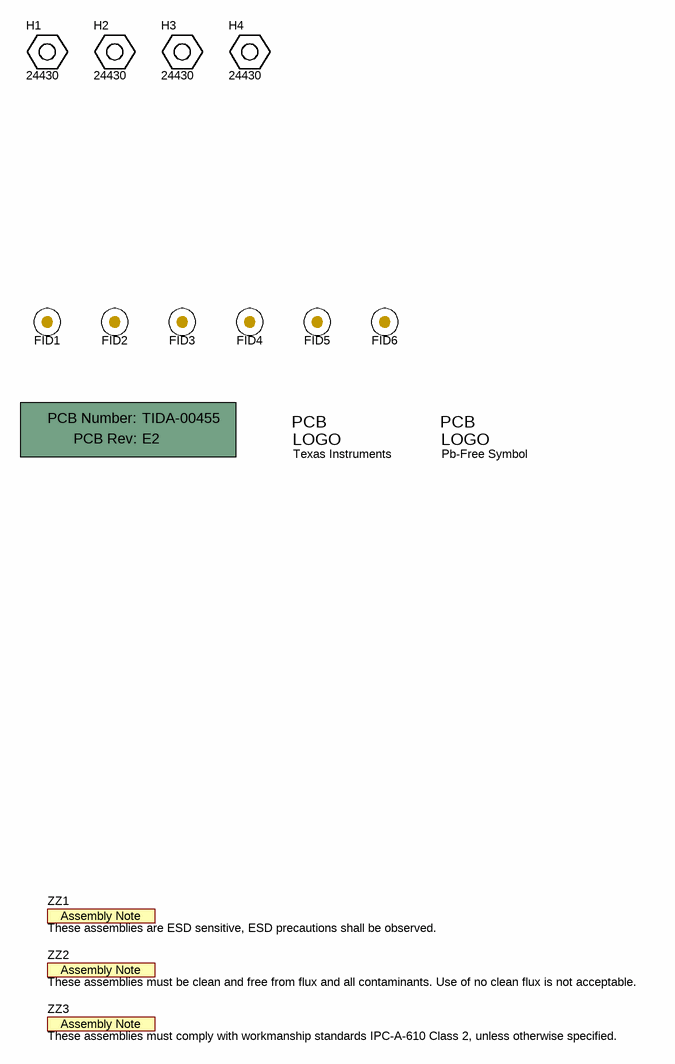
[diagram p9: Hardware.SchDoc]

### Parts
!PCB1  Printed Circuit Board  (value not drawn)  (mechanical)
FID1  Fiducial  [Fiducial10-20]  (value not drawn)
FID2  Fiducial  [Fiducial10-20]  (value not drawn)
FID3  Fiducial  [Fiducial10-20]  (value not drawn)
FID4  Fiducial  [Fiducial10-20]  (value not drawn)
FID5  Fiducial  [Fiducial10-20]  (value not drawn)
FID6  Fiducial  [Fiducial10-20]  (value not drawn)
H1  24430  (mechanical)
H2  24430  (mechanical)
H3  24430  (mechanical)
H4  24430  (mechanical)
Logo1  Texas Instruments  [TI_Stacked_SolderMask_Medium]  (no BOM)
Logo2  Pb-Free Symbol  [Pb-Free_Overlay_Small]  (no BOM)
ZZ1  These assemblies are ESD sensitive, ESD precautions shall be observed.  [AssemblyNote]  (no BOM)
ZZ2  These assemblies must be clean and free from flux and all contaminants. Use of no clean flux is not acceptable.  [AssemblyNote]  (no BOM)
ZZ3  These assemblies must comply with workmanship standards IPC-A-610 Class 2, unless otherwise specified.  [AssemblyNote]  (no BOM)

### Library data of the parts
!PCB1 = PCB: Manufacturer: Any; PartNumber: TIDA-00455; SymbolCreator: a0412235
FID1-FID6 = Fiducial: Fiducial mark.  There is nothing to buy or mount.; SymbolCreator: codlsc
H1-H4 = 24430: HEX Standoff M3 Aluminum 5 MM; Manufacturer: Keystone; SymbolCreator: a0412235
Logo1 = TI_Logo: Texas Instrument Corporate Signature; SymbolCreator: codlsc
Logo2 = Pb-Free: SymbolCreator: a0412235
ZZ1-ZZ3 = AssemblyNote: SymbolCreator: codlsc

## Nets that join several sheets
1V1: Camera_Switch_and_Bucks (J12.2), Deserializer (C92.1 L27.1 L28.1 L30.1)
1V8: Camera_Switch_and_Bucks (J10.2), Deserializer (8 pins), OV490_1 (5 pins), OV490_2 (5 pins)
3V3: Camera_Switch_and_Bucks (8 pins), Deserializer (C106.1 C107.1 C108.1 U1.16), OV490_1 (24 pins), OV490_2 (24 pins), uC (37 pins), TDA2x_Conector (J32.1)
EVM_1V8: Camera_Switch_and_Bucks (J10.3), TDA2x_Conector (J29.55 J29.56)
EVM_3V3: Camera_Switch_and_Bucks (J7.3), TDA2x_Conector (J29.57 J29.58 J29.59 J29.60)
EVM_12V: Camera_Switch_and_Bucks (J6.1 J8.1), TDA2x_Conector (6 pins)
GND: cam_connections (40 pins), V_Batt_Supply (33 pins), Camera_Switch_and_Bucks (50 pins), Deserializer (44 pins), OV490_1 (43 pins), OV490_2 (43 pins), uC (40 pins), TDA2x_Conector (21 pins)
V_CAM1: cam_connections (C3.1 C4.1 L1.2 TP1.1), Camera_Switch_and_Bucks (R32.1)
V_CAM2: cam_connections (C7.1 C8.1 L2.2 TP2.1), Camera_Switch_and_Bucks (R33.1)
V_CAM3: cam_connections (C17.1 C18.1 L9.2 TP3.1), Camera_Switch_and_Bucks (R34.1)
V_CAM4: cam_connections (C21.1 C22.1 L10.2 TP4.1), Camera_Switch_and_Bucks (R35.1)
V_MAIN: V_Batt_Supply (D7.2 R24.2), Camera_Switch_and_Bucks (J6.3 J8.3)
CAM_PW_CS: Camera_Switch_and_Bucks (U4.14), uC (U16.21)
CAM_PW_SW: Camera_Switch_and_Bucks (R185.2 U4.3), uC (U16.20)
CSI0_CLK_N: Deserializer (U1.22), OV490_1 (U8.H8)
CSI0_CLK_P: Deserializer (U1.23), OV490_1 (U8.J8)
CSI0_D0_N: Deserializer (U1.24), OV490_1 (U8.J6)
CSI0_D0_P: Deserializer (U1.25), OV490_1 (U8.J7)
CSI0_D1_N: Deserializer (U1.26), OV490_1 (U8.K7)
CSI0_D1_P: Deserializer (U1.27), OV490_1 (U8.K8)
CSI0_D2_N: Deserializer (U1.28), OV490_1 (U8.G8)
CSI0_D2_P: Deserializer (U1.29), OV490_1 (U8.G9)
CSI0_D3_N: Deserializer (U1.30), OV490_1 (U8.H9)
CSI0_D3_P: Deserializer (U1.31), OV490_1 (U8.H10)
CSI1_CLK_N: Deserializer (U1.34), OV490_2 (U12.H8)
CSI1_CLK_P: Deserializer (U1.35), OV490_2 (U12.J8)
CSI1_D0_N: Deserializer (U1.36), OV490_2 (U12.J6)
CSI1_D0_P: Deserializer (U1.37), OV490_2 (U12.J7)
CSI1_D1_N: Deserializer (U1.38), OV490_2 (U12.K7)
CSI1_D1_P: Deserializer (U1.39), OV490_2 (U12.K8)
CSI1_D2_N: Deserializer (U1.40), OV490_2 (U12.G8)
CSI1_D2_P: Deserializer (U1.41), OV490_2 (U12.G9)
CSI1_D3_N: Deserializer (U1.42), OV490_2 (U12.H9)
CSI1_D3_P: Deserializer (U1.43), OV490_2 (U12.H10)
CTS_SOC: uC (U16.24), TDA2x_Conector (J29.98)
DVP1_04: OV490_1 (U8.C4), TDA2x_Conector (R190.2)
DVP1_05: OV490_1 (U8.B4), TDA2x_Conector (R191.1)
DVP1_06: OV490_1 (U8.A4), TDA2x_Conector (R192.2)
DVP1_07: OV490_1 (U8.A3), TDA2x_Conector (R193.1)
DVP1_08: OV490_1 (U8.B3), TDA2x_Conector (R194.2)
DVP1_09: OV490_1 (U8.B2), TDA2x_Conector (R195.1)
DVP1_10: OV490_1 (U8.D3), TDA2x_Conector (R196.2)
DVP1_11: OV490_1 (U8.C2), TDA2x_Conector (R197.1)
DVP1_HSYNC: OV490_1 (U8.A2), TDA2x_Conector (R174.1)
DVP1_PCLK: OV490_1 (U8.B1), TDA2x_Conector (R198.2)
DVP1_VSYNC: OV490_1 (U8.C1), TDA2x_Conector (R175.2)
DVP2_04: OV490_2 (U12.C4), TDA2x_Conector (R211.1)
DVP2_05: OV490_2 (U12.B4), TDA2x_Conector (R212.2)
DVP2_06: OV490_2 (U12.A4), TDA2x_Conector (R209.1)
DVP2_07: OV490_2 (U12.A3), TDA2x_Conector (R210.2)
DVP2_08: OV490_2 (U12.B3), TDA2x_Conector (R207.1)
DVP2_09: OV490_2 (U12.B2), TDA2x_Conector (R208.2)
DVP2_10: OV490_2 (U12.D3), TDA2x_Conector (R205.1)
DVP2_11: OV490_2 (U12.C2), TDA2x_Conector (R206.2)
DVP2_HSYNC: OV490_2 (U12.A2), TDA2x_Conector (R151.1)
DVP2_PCLK: OV490_2 (U12.B1), TDA2x_Conector (R213.1)
DVP2_VSYNC: OV490_2 (U12.C1), TDA2x_Conector (R221.1)
FRAME_SYNC_OV1: OV490_1 (U8.F5), TDA2x_Conector (J29.32)
FRAME_SYNC_OV2: OV490_2 (U12.F5), TDA2x_Conector (J29.34)
FSIN0_OV1: OV490_1 (R64.1 R158.1 U8.C9), uC (R163.1)
FSIN0_OV2: OV490_2 (R94.1 R161.1 U12.C9), uC (R165.1)
FSIN1_OV1: OV490_1 (R68.2 R157.1 U8.A7), uC (R164.1)
FSIN1_OV2: OV490_2 (R98.2 R160.1 U12.A7), uC (R166.1)
GPIO0_OV1: OV490_1 (U8.C10), uC (J34.1)
GPIO0_OV2: OV490_2 (U12.C10), uC (J35.1)
GPIO0_SOC: uC (J37.1), TDA2x_Conector (J29.89)
GPIO0_UB960: Deserializer (U1.9), uC (J33.16)
GPIO1_OV1: OV490_1 (U8.C8), uC (J34.3)
GPIO1_OV2: OV490_2 (U12.C8), uC (J35.3)
GPIO1_SOC: uC (J37.3), TDA2x_Conector (J29.90)
GPIO1_UB960: Deserializer (U1.10), uC (J33.14)
GPIO2_OV1: OV490_1 (R62.1 U8.J3), uC (J34.5)
GPIO2_OV2: OV490_2 (R92.1 U12.J3), uC (J35.5)
GPIO2_SOC: uC (J37.5), TDA2x_Conector (J29.91)
GPIO2_UB960: Deserializer (U1.14), uC (J33.12)
GPIO3_OV1: OV490_1 (U8.H3), uC (J34.7)
GPIO3_OV2: OV490_2 (U12.H3), uC (J35.7)
GPIO3_SOC: uC (J37.7), TDA2x_Conector (J29.92)
GPIO3_UB960: Deserializer (U1.15), uC (J33.10)
GPIO4_OV1: OV490_1 (U8.H4), uC (J34.9)
GPIO4_OV2: OV490_2 (U12.H4), uC (J35.9)
GPIO4_SOC: uC (J37.9), TDA2x_Conector (J29.93)
GPIO4_UB960: Deserializer (U1.17), uC (J33.8)
GPIO5_OV1: OV490_1 (U8.G5), uC (J34.11)
GPIO5_OV2: OV490_2 (U12.G5), uC (J35.11)
GPIO5_SOC: uC (J37.11), TDA2x_Conector (J29.94)
GPIO5_UB960: Deserializer (U1.18), uC (J33.6)
GPIO6_SOC: uC (J37.13), TDA2x_Conector (J29.95)
GPIO6_UB960: Deserializer (U1.19), uC (J33.4)
GPIO7_SOC: uC (J37.15), TDA2x_Conector (J29.96)
GPIO7_UB960: Deserializer (U1.20), uC (J33.2)
I2C_SCL_EXT: uC (J27.2 R172.1 U19.3), TDA2x_Conector (J25.1)
I2C_SCL_OV1: Deserializer (U1.12), OV490_1 (J16.2 R56.1 U8.D10), uC (U18.3)
I2C_SCL_OV2: Deserializer (U1.8), OV490_2 (J18.2 R86.1 U12.D10)
I2C_SCL_SOC: uC (J20.2 R121.1 U17.3), TDA2x_Conector (R186.2)
I2C_SCL_UC: OV490_1 (U8.E2), OV490_2 (U12.E2), uC (7 pins)
I2C_SDA_EXT: uC (J27.3 R171.1 U19.4), TDA2x_Conector (J25.3)
I2C_SDA_OV1: Deserializer (U1.11), OV490_1 (J16.3 R57.1 U8.D9), uC (U18.4)
I2C_SDA_OV2: Deserializer (U1.7), OV490_2 (J18.3 R87.1 U12.D9)
I2C_SDA_SOC: uC (J20.3 R122.1 U17.4), TDA2x_Conector (R152.2)
I2C_SDA_UC: OV490_1 (U8.D1), OV490_2 (U12.D1), uC (7 pins)
nRESET_OV1: OV490_1 (R159.2), uC (U16.27)
nRESET_OV2: OV490_2 (R162.2), uC (U16.28)
nRESET_SOC: uC (U16.22), TDA2x_Conector (R214.2)
PDB_UB960: Deserializer (R154.2), uC (U16.17)
PG_3V3: Camera_Switch_and_Bucks (J11.1 R36.1 U3.2 U5.8), uC (R156.2)
PWDN_OV1: OV490_1 (R133.2 U8.F2), uC (U16.18)
PWDN_OV2: OV490_2 (R137.2 U12.F2), uC (U16.19)
RIN0_N: cam_connections (C11.2), Deserializer (U1.51)
RIN0_P: cam_connections (C9.1), Deserializer (U1.50)
RIN1_N: cam_connections (C12.2), Deserializer (U1.54)
RIN1_P: cam_connections (C10.1), Deserializer (U1.53)
RIN2_N: cam_connections (C25.2), Deserializer (U1.60)
RIN2_P: cam_connections (C23.1), Deserializer (U1.59)
RIN3_N: cam_connections (C26.2), Deserializer (U1.63)
RIN3_P: cam_connections (C24.1), Deserializer (U1.62)
RTS_SOC: uC (U16.23), TDA2x_Conector (J29.97)
SPI_CLK_OV1: OV490_1 (R63.2 R71.1 U10.6), TDA2x_Conector (J25.7 J31.5 J32.5)
SPI_CLK_OV2: OV490_2 (R93.2 R101.1 U14.6), TDA2x_Conector (J31.6)
SPI_CS_OV1: OV490_1 (R59.1 R73.1 U10.1), TDA2x_Conector (J32.6 J40.1)
SPI_CS_OV2: OV490_2 (R89.1 R103.1 U14.1), TDA2x_Conector (J32.7 J40.3)
SPI_MISO_OV1: OV490_1 (R69.1 U10.2), TDA2x_Conector (J25.5 J31.1 J32.3)
SPI_MISO_OV2: OV490_2 (R99.1 U14.2), TDA2x_Conector (J31.2)
SPI_MOSI_OV1: OV490_1 (R70.1 U10.5), TDA2x_Conector (J25.8 J31.3 J32.4)
SPI_MOSI_OV2: OV490_2 (R100.1 U14.5), TDA2x_Conector (J31.4)
SYS_CLK_25MHZ: Deserializer (R46.2), OV490_1 (R80.1), OV490_2 (R110.1)

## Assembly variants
001: not fitted C29 C36 C39 C46 C50 C53 FID1 FID2 FID3 FID4 FID5 FID6 R25 R46 R49 R80 R82 R85 R110 R114 R115 R142 TP16 TP17 TP18 TP19 TP20 TP21 TP22 TP23 TP29 TP30 TP31 TP32 TP33 TP34 TP35 TP36 TP37 TP38 TP39 TP40 TP41 TP42 TP47 TP48 TP49 TP50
